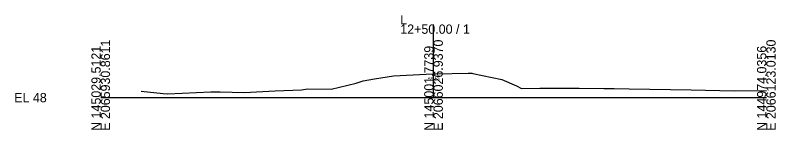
# Model space of a CAD drawing. Extents: x -26 to 203, y -10 to 20020.
# Drawn here: x -25.7 to 202.8, y 490.3 to 524.8 of the extents above; entities that cross this region are included whole.
import ezdxf

# ---------------------------------------------------------------- set-up
doc = ezdxf.new("R2010")
doc.units = 0
for name, color, linetype in [('Default', 7, 'Continuous'), ('Exist Cross Section Cell', 7, 'Continuous'), ('Exist XS Center Line Elevation Label', 7, 'Continuous'), ('Exist XS Ground Line', 7, 'Continuous')]:
    doc.layers.add(name, color=color, linetype=linetype)

msp = doc.modelspace()

# ---------------------------------------------------------------- linework, layer by layer
at = {"layer": 'Exist Cross Section Cell'}
for p, q in [((100, 500), (100, 522.03)), ((0, 500), (100, 500)), ((100, 500), (200, 500))]:
    msp.add_line(p, q, dxfattribs=at)
at = {"layer": 'Exist XS Ground Line'}
for p, q in [((110.4, 507.33), (111.55, 507.34)), ((111.55, 507.34), (111.83, 507.29)), ((76.73, 504.39), (78.82, 505.07)), ((78.82, 505.07), (82.27, 505.69)), ((82.27, 505.69), (88.01, 506.61)), ((88.01, 506.61), (97.79, 507.02)), ((97.79, 507.02), (100, 507.13)), ((100, 507.13), (100.68, 507.16)), ((100.68, 507.16), (110.4, 507.33)), ((111.83, 507.29), (120.49, 505.51)), ((120.49, 505.51), (124.94, 503.52)), ((69.27, 502.6), (76.73, 504.39)), ((124.94, 503.52), (126.41, 502.72)), ((126.41, 502.72), (131.98, 502.85)), ((131.98, 502.85), (140.44, 502.88)), ((140.44, 502.88), (143.76, 502.82)), ((143.76, 502.82), (151.13, 502.76)), ((12.15, 501.98), (18.8, 501.27)), ((18.8, 501.27), (20.18, 501.18)), ((20.18, 501.18), (33.07, 501.73)), ((33.07, 501.73), (35.88, 501.78)), ((35.88, 501.78), (43.15, 501.59)), ((43.15, 501.59), (52.42, 502)), ((52.42, 502), (60.35, 502.38)), ((60.35, 502.38), (62.16, 502.63)), ((62.16, 502.63), (69.27, 502.6)), ((151.13, 502.76), (154.27, 502.72)), ((154.27, 502.72), (158.83, 502.64)), ((158.83, 502.64), (177.43, 502.34)), ((177.43, 502.34), (190.35, 502.05)), ((190.35, 502.05), (200, 502.15))]:
    msp.add_line(p, q, dxfattribs=at)

# ---------------------------------------------------------------- texts
at = {"layer": 'Default'}
msp.add_text('-', height=0.00001, dxfattribs=at).set_placement((0, 500))
at = {"layer": 'Exist Cross Section Cell'}
for s, p in [('L', (90, 522.03)), ('12+50.00 / 1', (90, 519.23)), ('EL 48', (-26, 498.6))]:
    msp.add_text(s, height=2.8, dxfattribs=at).set_placement(p)
for s, p in [('E 2065930.8611', (2.8, 490)), ('E 2066026.9370', (102.8, 490)), ('E 2066123.0130', (202.8, 490)), ('N 145029.5121', (0, 490)), ('N 145001.7739', (100, 490)), ('N 144974.0356', (200, 490))]:
    msp.add_text(s, height=2.8, rotation=90, dxfattribs=at).set_placement(p)
at = {"layer": 'Exist XS Center Line Elevation Label'}
msp.add_text('55.13', height=1, dxfattribs=at).set_placement((98.39, 505.13))

doc.saveas('drawing.dxf')
